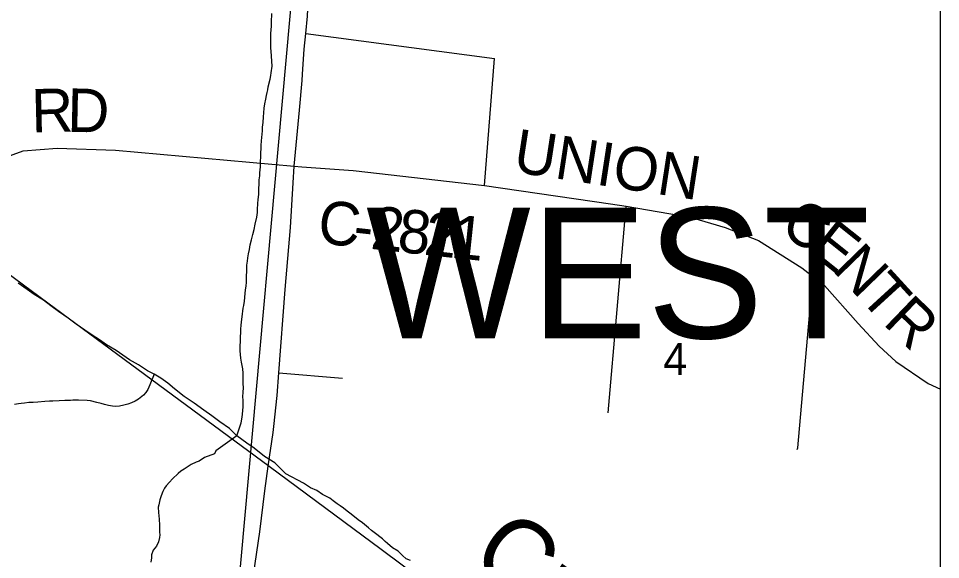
# Model space of a CAD drawing. Extents: x 0 to 34, y 0 to 22.
# Drawn here: x 14.895 to 16.1, y 17.283 to 17.99 of the extents above; entities that cross this region are included whole.
import ezdxf

# ---------------------------------------------------------------- set-up
doc = ezdxf.new("R2010")
doc.units = 0
for name, color, linetype in [('GM_X_County_Road', 7, 'Continuous'), ('GM_X_County_Road_Text', 7, 'Continuous'), ('GM_X_Minor_River', 7, 'Continuous'), ('GM_X_Minor_River_Text', 7, 'Continuous'), ('GM_X_Rail_Line', 7, 'Continuous'), ('GM_X_Section', 7, 'Continuous'), ('GM_X_Section_Text', 7, 'Continuous'), ('GM_X_State_Route', 7, 'Continuous'), ('GM_X_Township_Road', 7, 'Continuous'), ('GM_X_Township_Text', 7, 'Continuous'), ('GM_X_Unincorporated', 7, 'Continuous'), ('SC_Scratch1', 7, 'Continuous'), ('SH_Border', 7, 'Continuous'), ('SH_Cut_Line', 7, 'Continuous')]:
    doc.layers.add(name, color=color, linetype=linetype)

msp = doc.modelspace()

# ---------------------------------------------------------------- linework, layer by layer
at = {"layer": 'GM_X_County_Road'}
for points in [[(14.2077, 17.7607), (14.3462, 17.6814), (14.4062, 17.6431), (14.4661, 17.6177), (14.5111, 17.6094), (14.5628, 17.6109), (14.6229, 17.6258), (14.6669, 17.6484), (14.7268, 17.6959), (14.8037, 17.7607), (14.8271, 17.7802), (14.8566, 17.8006), (14.901, 17.8166), (14.9456, 17.8203), (15.0217, 17.8178), (15.2553, 17.7966), (15.2653, 17.796)], [(15.2653, 17.796), (15.3324, 17.7913), (15.504, 17.7714), (15.6686, 17.7474), (15.6893, 17.7444), (15.7727, 17.7301), (15.8187, 17.7167), (15.8621, 17.6997), (15.9188, 17.664), (15.9485, 17.6407), (15.9924, 17.5914), (16.0199, 17.5614), (16.0414, 17.5414), (16.0839, 17.5129), (16.1, 17.5052)]]:
    msp.add_lwpolyline(points, dxfattribs=at)
at = {"layer": 'GM_X_Minor_River'}
for points in [[(15.2103, 17.788), (15.2112, 17.796), (15.2113, 17.8017), (15.2119, 17.8104), (15.2121, 17.8237), (15.2126, 17.8298), (15.214, 17.8431), (15.2141, 17.8477), (15.2146, 17.8537), (15.2152, 17.8613), (15.2157, 17.8666), (15.2162, 17.8727), (15.217, 17.8784), (15.2183, 17.8845), (15.2191, 17.889), (15.22, 17.8932), (15.2208, 17.8966), (15.2213, 17.9004), (15.2237, 17.9106), (15.2246, 17.9151), (15.2254, 17.9189), (15.2264, 17.9273), (15.2261, 17.9341), (15.2255, 17.9406), (15.2252, 17.9471), (15.2249, 17.9509), (15.225, 17.9551), (15.2249, 17.9653), (15.225, 17.9699), (15.2255, 17.9798), (15.2256, 17.9851), (15.2262, 17.9961)], [(15.1803, 17.4445), (15.1859, 17.4614), (15.1867, 17.4664), (15.1876, 17.4724), (15.1881, 17.4778), (15.1885, 17.4819), (15.1887, 17.4911), (15.1884, 17.4956), (15.1886, 17.5017), (15.189, 17.507), (15.1888, 17.5127), (15.1887, 17.5264), (15.188, 17.5321), (15.1863, 17.5405), (15.1857, 17.5459), (15.1847, 17.5554), (15.1851, 17.574), (15.1856, 17.579), (15.1857, 17.5839), (15.1862, 17.5889), (15.1866, 17.593), (15.1876, 17.604), (15.1881, 17.6074), (15.1885, 17.6112), (15.1894, 17.6146), (15.1902, 17.6203), (15.1912, 17.6306), (15.1917, 17.6351), (15.1925, 17.6401), (15.193, 17.6454), (15.1935, 17.6674), (15.1943, 17.6727), (15.1948, 17.6769), (15.1956, 17.6822), (15.1969, 17.6879), (15.1978, 17.694), (15.1994, 17.7004), (15.2011, 17.7076), (15.2031, 17.714), (15.2044, 17.7208), (15.2065, 17.7303), (15.2073, 17.7364), (15.2074, 17.7402), (15.2079, 17.7478), (15.2084, 17.7531), (15.2089, 17.7599), (15.2091, 17.7668), (15.2096, 17.7743), (15.2097, 17.7789), (15.2102, 17.7842), (15.2103, 17.788)], [(15.2446, 17.3947), (15.2302, 17.4092), (15.2164, 17.4176), (15.203, 17.4282), (15.1934, 17.435), (15.1803, 17.4445), (15.1707, 17.4539), (15.1581, 17.4627), (15.1477, 17.4706), (15.1372, 17.4781), (15.1246, 17.4869), (15.1115, 17.496), (15.0989, 17.5059), (15.09, 17.5134), (15.0811, 17.5198), (15.0725, 17.525), (15.0635, 17.5294), (15.0519, 17.537), (15.04, 17.5438), (15.0228, 17.5561), (15.0101, 17.5634), (15.0008, 17.5697), (14.9911, 17.5761), (14.9818, 17.5825), (14.9703, 17.5904), (14.9598, 17.598), (14.9475, 17.6067), (14.9371, 17.6143), (14.9275, 17.6218), (14.9155, 17.629), (14.9062, 17.6357), (14.8947, 17.6437)], [(15.0725, 17.525), (15.0667, 17.5111), (15.0639, 17.5051), (15.0615, 17.501), (15.0584, 17.4977), (15.0517, 17.4922), (15.0475, 17.4896), (15.0429, 17.4875), (15.0379, 17.4857), (15.0325, 17.4844), (15.0272, 17.4834), (15.0222, 17.4828), (15.0177, 17.4833), (15.0127, 17.4842), (15.0075, 17.4855), (15.0029, 17.4868), (14.9976, 17.4881), (14.989, 17.4903), (14.9848, 17.4908), (14.9734, 17.4911), (14.9662, 17.491), (14.9628, 17.4907), (14.9555, 17.4905), (14.9483, 17.49), (14.9399, 17.4899), (14.9354, 17.4896), (14.9293, 17.4891), (14.9201, 17.4886), (14.914, 17.488), (14.9087, 17.4878), (14.903, 17.4872), (14.8984, 17.4866), (14.895, 17.4863), (14.8896, 17.4853)], [(15.1803, 17.4445), (15.1528, 17.4248), (15.1511, 17.4211), (15.1381, 17.4162), (15.1311, 17.4114), (15.1272, 17.41), (15.1207, 17.4068), (15.1114, 17.401), (15.1071, 17.3981), (15.1036, 17.3952), (15.0962, 17.3882), (15.0923, 17.3841), (15.088, 17.3793), (15.086, 17.3759), (15.0835, 17.3715), (15.0815, 17.3662), (15.0798, 17.3609), (15.0785, 17.3545), (15.0776, 17.3511), (15.0782, 17.3443), (15.0784, 17.3397), (15.0787, 17.3355), (15.0792, 17.3279), (15.0795, 17.3233), (15.0793, 17.3187), (15.0796, 17.3149), (15.0795, 17.3115), (15.0782, 17.3059), (15.0754, 17.3002), (15.071, 17.2951), (15.069, 17.289), (15.0688, 17.2849), (15.0679, 17.2792)], [(15.4072, 17.2815), (15.4015, 17.2839), (15.3967, 17.2882), (15.3911, 17.2936), (15.384, 17.298), (15.3774, 17.3038), (15.374, 17.3065), (15.3707, 17.3097), (15.3673, 17.3124), (15.3632, 17.3155), (15.3565, 17.3206), (15.3524, 17.3241), (15.3446, 17.3307), (15.3387, 17.3347), (15.3297, 17.3421), (15.3245, 17.346), (15.3197, 17.3499), (15.3152, 17.353), (15.3115, 17.3554), (15.3063, 17.3597), (15.3018, 17.3628), (15.2925, 17.368), (15.285, 17.3731), (15.2768, 17.3766), (15.2674, 17.3825), (15.2446, 17.3947)]]:
    msp.add_lwpolyline(points, dxfattribs=at)
at = {"layer": 'GM_X_Rail_Line'}
msp.add_lwpolyline([(16.1, 16.1129), (15.9532, 16.3984), (15.8905, 16.5208), (15.7619, 16.7709), (15.6306, 17.0265), (15.6177, 17.0502), (15.6059, 17.0706), (15.5946, 17.0881), (15.5817, 17.1067), (15.5702, 17.1218), (15.5559, 17.1388), (15.5412, 17.1554), (15.5178, 17.1786), (15.5017, 17.1934), (15.4851, 17.2077), (15.4678, 17.2221), (15.453, 17.2332), (15.3691, 17.2959), (15.2224, 17.4044), (14.9335, 17.6179), (14.4589, 17.9682), (14.3622, 18.0403)], dxfattribs=at)
at = {"layer": 'GM_X_Section'}
msp.add_lwpolyline([(15.2638, 18.1527), (15.1713, 17.1233), (14.1379, 16.9974), (14.223, 17.9945)], close=True, dxfattribs=at)
at = {"layer": 'GM_X_State_Route'}
for points in [[(15.2656, 17.9088), (15.2663, 17.917), (15.2685, 17.9495), (15.2707, 17.97), (15.2728, 17.9927), (15.2744, 18.0293), (15.2749, 18.0513), (15.275, 18.0697), (15.2743, 18.1103), (15.2728, 18.1629)], [(15.2286, 17.4566), (15.233, 17.4971), (15.2354, 17.5268), (15.2434, 17.6355), (15.2505, 17.7165), (15.2539, 17.7751), (15.2553, 17.7966), (15.2624, 17.8701), (15.2656, 17.9088)], [(15.1266, 16.6616), (15.1304, 16.7092), (15.1352, 16.7672), (15.1423, 16.8402), (15.148, 16.8856), (15.1505, 16.9097), (15.1538, 16.9543), (15.1603, 17.0566), (15.1676, 17.1161), (15.1754, 17.1424), (15.1804, 17.1571), (15.1857, 17.1784), (15.1919, 17.2036), (15.1961, 17.2231), (15.202, 17.2627), (15.2102, 17.3192), (15.2168, 17.3724), (15.2212, 17.4049), (15.2277, 17.4487), (15.2286, 17.4566)]]:
    msp.add_lwpolyline(points, dxfattribs=at)
at = {"layer": 'GM_X_Township_Road'}
for p, q in [((15.2707, 17.97), (15.5172, 17.9376)), ((15.504, 17.7714), (15.5172, 17.9376)), ((15.6658, 17.4747), (15.6893, 17.7444)), ((15.2354, 17.5268), (15.3185, 17.5199))]:
    msp.add_line(p, q, dxfattribs=at)
msp.add_lwpolyline([(15.9126, 17.4267), (15.9135, 17.4287), (15.9286, 17.6016), (15.9288, 17.6031), (15.9293, 17.6061), (15.9299, 17.6087), (15.9306, 17.6114), (15.9313, 17.6138), (15.9322, 17.6161), (15.9332, 17.6187), (15.9344, 17.6211), (15.9357, 17.624), (15.937, 17.6261), (15.9386, 17.6286), (15.9399, 17.6306), (15.9421, 17.6335), (15.9448, 17.6366), (15.9485, 17.6407)], dxfattribs=at)
at = {"layer": 'GM_X_Unincorporated'}
msp.add_lwpolyline([(16.1, 16.9781), (16.1, 18.0118), (15.2638, 18.1527), (15.1713, 17.1233)], close=True, dxfattribs=at)
at = {"layer": 'SC_Scratch1'}
msp.add_lwpolyline([(16.1, 14.8738), (16.1, 19.8941), (16.0684, 19.8968), (15.8849, 19.9144), (15.653, 19.9317), (15.4403, 19.9472), (15.2122, 19.9649), (15.0267, 19.9781), (14.9403, 19.9853), (14.9338, 19.9858), (14.6885, 20.0053), (14.609, 20.0113), (14.5282, 20.0174), (14.3921, 20.0277), (14.3035, 19.1497), (14.1911, 17.7706), (14.1894, 17.7492), (14.1791, 17.6233), (14.1287, 17.0041), (14.1092, 16.7637), (14.0483, 15.9927), (14.0411, 15.8502)], dxfattribs=at)
at = {"layer": 'SH_Border'}
msp.add_lwpolyline([(9.3, 20.2361), (9.3, 13.4361), (16.1, 13.4361), (16.1, 20.2361)], close=True, dxfattribs=at)
at = {"layer": 'SH_Cut_Line'}
msp.add_lwpolyline([(16.1, 14.8738), (16.1, 20.2361), (9.3, 20.2361), (9.3, 15.5386)], dxfattribs=at)

# ---------------------------------------------------------------- texts
at = {"layer": 'GM_X_County_Road_Text'}
for s, height, rotation, p in [('R', 0.0568, 1.4228, (14.9124, 17.8406)), ('D', 0.0568, 358.8032, (14.9584, 17.8417)), ('UNION', 0.05682, 351.2378, (15.5399, 17.7896)), ('C', 0.0568, 353.6702, (15.2844, 17.6966)), ('2', 0.0568, 353.6746, (15.354, 17.6889)), ('8', 0.0568, 353.6928, (15.3888, 17.6851)), ('C', 0.0568, 326.3451, (15.8878, 17.7113)), ('2', 0.0568, 353.7588, (15.4236, 17.6812)), ('1', 0.0568, 353.9991, (15.4587, 17.6774)), ('E', 0.0568, 321.4684, (15.9256, 17.6862)), ('-', 0.0568, 353.6684, (15.3308, 17.6915)), ('N', 0.0568, 314.1319, (15.9574, 17.661)), ('T', 0.0568, 312.4021, (15.9919, 17.6254)), ('R', 0.0568, 316.09, (16.0234, 17.5912))]:
    msp.add_text(s, height=height, rotation=rotation, dxfattribs=at).set_placement(p)
at = {"layer": 'GM_X_Minor_River_Text'}
msp.add_text('Creek', height=0.0947, rotation=324.0162, dxfattribs=at).set_placement((15.482, 17.2774))
at = {"layer": 'GM_X_Section_Text'}
msp.add_text('4', height=0.0419, rotation=0, dxfattribs=at).set_placement((15.7377, 17.5237))
at = {"layer": 'GM_X_Township_Text'}
msp.add_text('WEST', height=0.17045, rotation=0, dxfattribs=at).set_placement((15.3493, 17.572))

doc.saveas('drawing.dxf')
